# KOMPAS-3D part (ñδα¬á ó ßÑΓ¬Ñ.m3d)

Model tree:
1. Эскиз:1
2. Операция выдавливания:1
     Расстояние 1 = 2.5
3. Эскиз:2
4. Операция выдавливания:2
     Расстояние 1 = 2.5
5. Эскиз:3
6. Вырезать элемент выдавливания:1
     Расстояние 1 = 2.5
